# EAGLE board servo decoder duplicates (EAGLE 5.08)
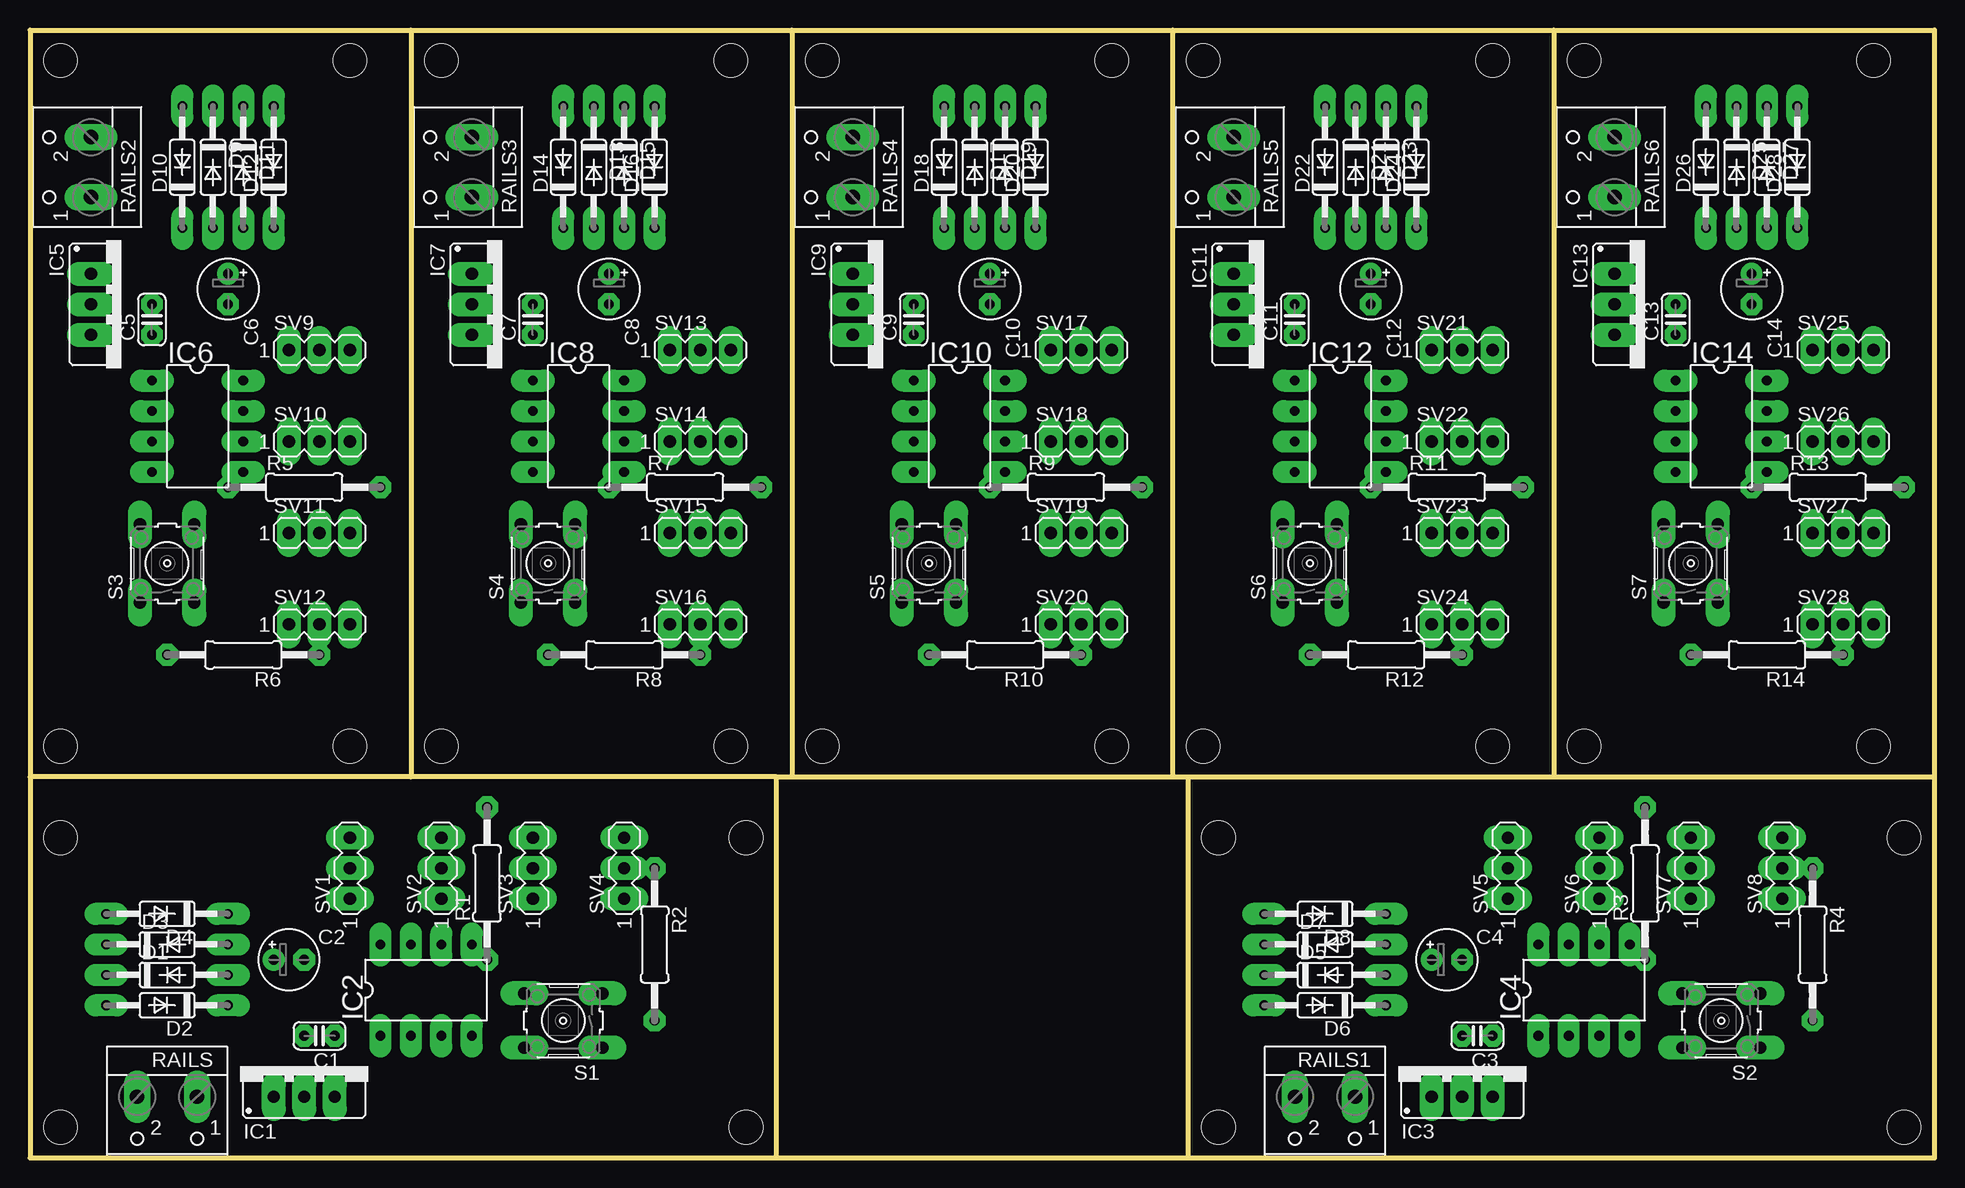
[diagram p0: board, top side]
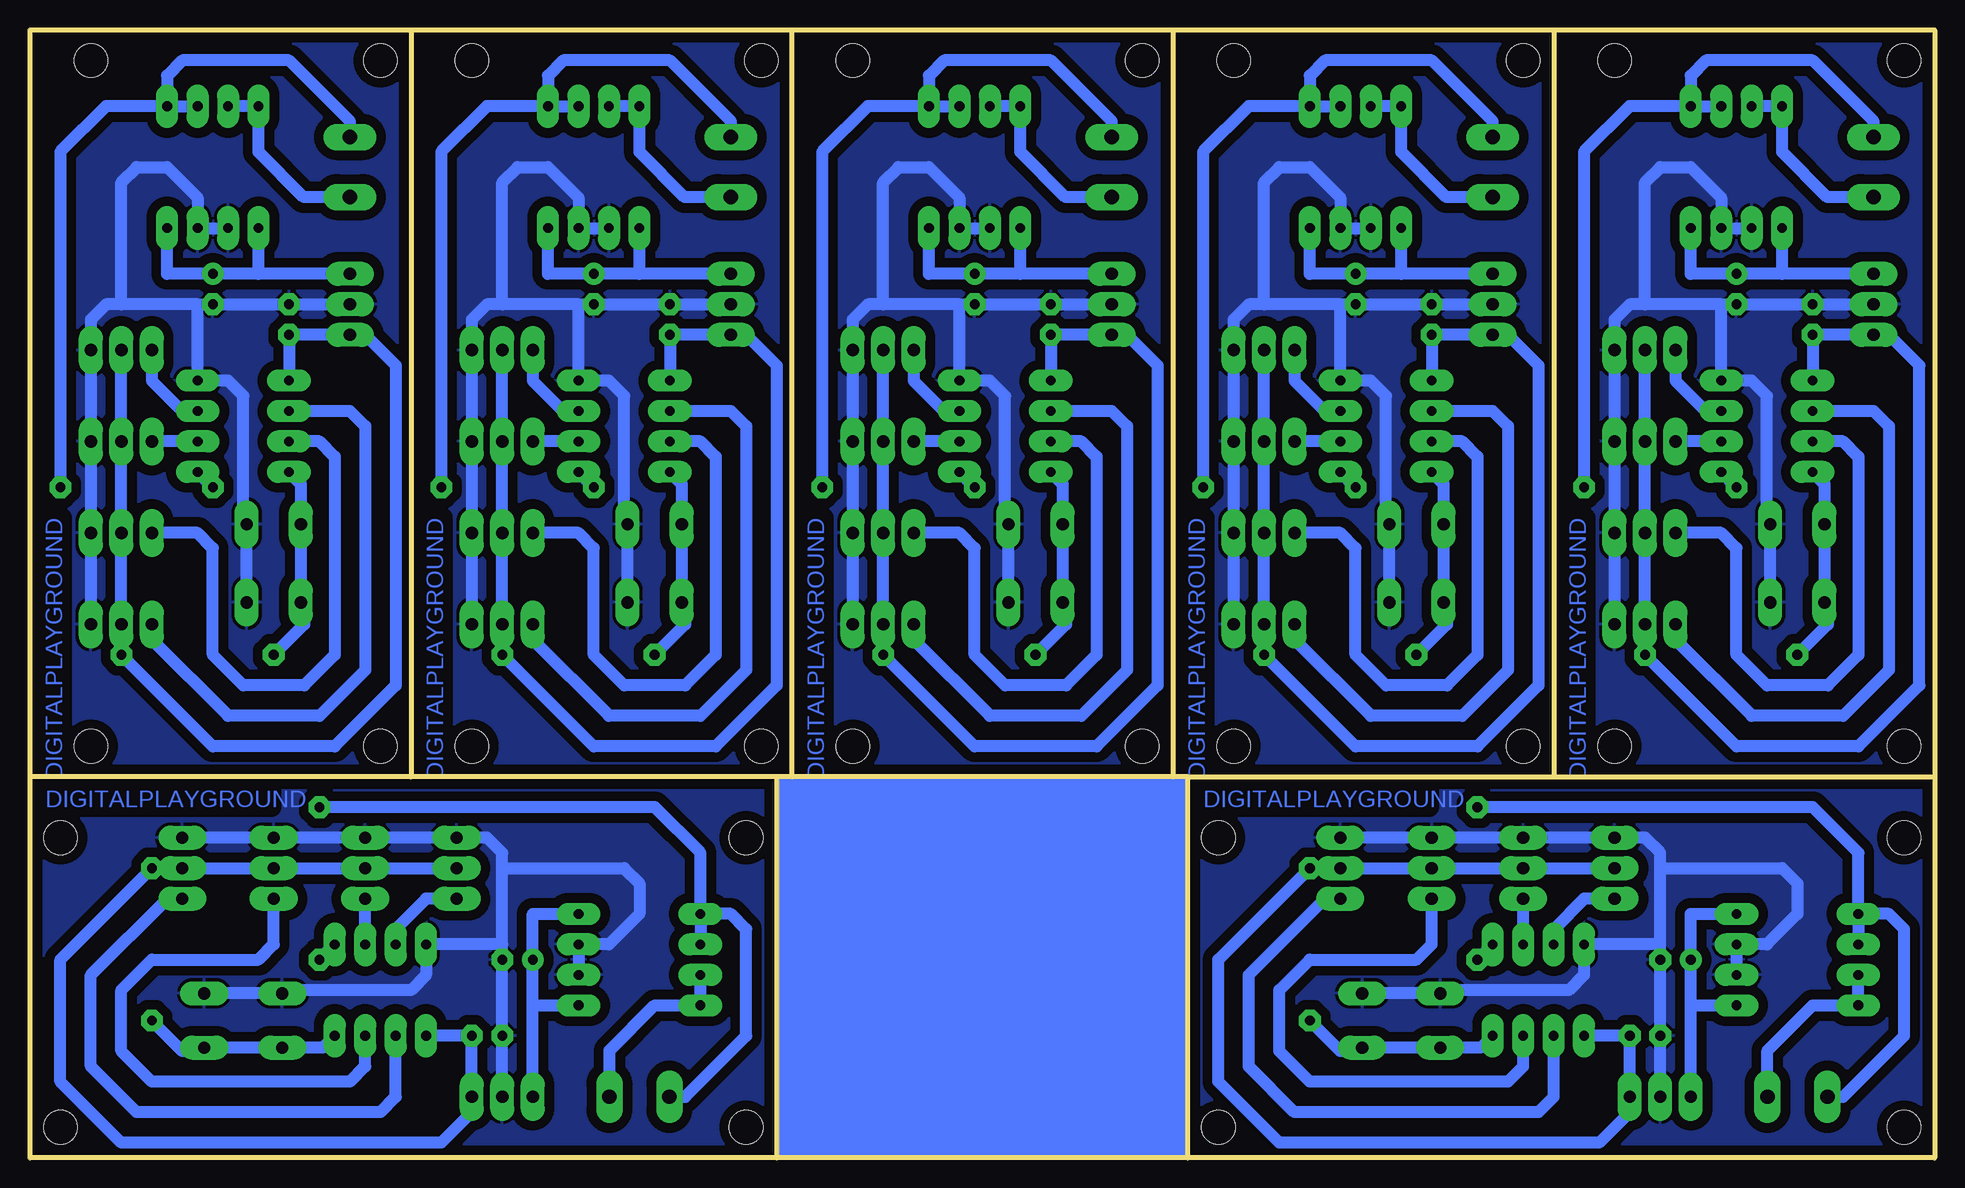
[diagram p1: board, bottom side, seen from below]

Size 158.75 x 93.98 mm. Coordinates in mm from the lower left corner, seen from the top.
Outline: 62.23,0 0,0 0,31.75
Outline: 62.23,0 96.52,0
Outline: 96.52,0 158.75,0 158.75,31.75
Outline: 158.75,31.75 158.75,93.98 127,93.98
Outline: 0,31.75 0,93.98 31.75,93.98
Outline: 62.23,0 62.23,31.75
Outline: 62.23,31.75 31.75,31.75
Outline: 31.75,31.75 0,31.75
Outline: 62.23,31.75 63.5,31.75
Outline: 63.5,31.75 95.25,31.75
Outline: 95.25,31.75 96.52,31.75
Outline: 31.75,93.98 63.5,93.98
Outline: 63.5,93.98 95.25,93.98
Outline: 31.75,93.98 31.75,31.75
Outline: 63.5,93.98 63.5,31.75
Outline: 96.52,31.75 127,31.75
Outline: 127,31.75 158.75,31.75
Outline: 96.52,31.75 96.52,0
Outline: 95.25,93.98 127,93.98
Outline: 95.25,31.75 95.25,93.98
Outline: 127,93.98 127,31.75
Copper layers (1*16): Top 0.8mm / dielectric 1.3mm / Bottom 0.8mm
Design rules "DRC settings smallest": minimum track width 0.8mm, minimum drill 24mil, track to track 0.2mm, track to pad 0.2mm, pad to pad 0.2mm, via to via 0.2mm, smd to smd 8mil, copper to edge 0.3mm, drill to drill 0.3mm, minimum pad ring 0.5mm, minimum via ring 1mm, stop-mask expansion 4mil, vias tented up to drill 0mil, thermal gap 10mil
Holes 2.8 mm at 2.54,26.67 59.69,26.67 59.69,2.54 2.54,2.54 99.06,26.67 156.21,26.67 156.21,2.54 99.06,2.54 26.67,91.44 26.67,34.29 2.54,34.29 2.54,91.44 58.42,91.44 58.42,34.29 34.29,34.29 34.29,91.44 90.17,91.44 90.17,34.29 66.04,34.29 66.04,91.44 121.92,91.44 121.92,34.29 97.79,34.29 97.79,91.44 153.67,91.44 153.67,34.29 129.54,34.29 129.54,91.44

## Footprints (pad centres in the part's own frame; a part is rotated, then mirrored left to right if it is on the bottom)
C025-024X044 = drill 0.813 octagon: 1 -1.27,0; 2 1.27,0
E2,5-5 = drill 0.813 pad 1.6 round: + -1.27,0 | drill 0.813 pad 1.6 octagon: - 1.27,0
DO35-10 = drill 0.813 long: A 5.08,0; C -5.08,0
78XXS = drill 1.016 long: GND 0,-2.54; IN -2.54,-2.54; OUT 2.54,-2.54
DIL8 = drill 0.813 long: 1 -3.81,-3.81; 2 -1.27,-3.81; 3 1.27,-3.81; 4 3.81,-3.81; 5 3.81,3.81; 6 1.27,3.81; 7 -1.27,3.81; 8 -3.81,3.81
0207/12 = drill 0.813 octagon: 1 -6.35,0; 2 6.35,0
W237-102 = drill 1.194 long: 1 -2.5,-1.27; 2 2.5,-1.27
B3F-10XX = drill 1.016 long: 1 -3.251,2.261; 2 3.251,2.261; 3 -3.251,-2.261; 4 3.251,-2.261
MA03-1 = drill 1.016 long: 1 -2.54,0; 2 0,0; 3 2.54,0

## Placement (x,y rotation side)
C1  100nF  [C025-024X044]  24.13,10.16 180 top
C2  100uF  [E2,5-5]  21.59,16.51 0 top
C3  100nF  [C025-024X044]  120.65,10.16 180 top
C4  100uF  [E2,5-5]  118.11,16.51 0 top
C5  100nF  [C025-024X044]  10.16,69.85 90 top
C6  100uF  [E2,5-5]  16.51,72.39 270 top
C7  100nF  [C025-024X044]  41.91,69.85 90 top
C8  100uF  [E2,5-5]  48.26,72.39 270 top
C9  100nF  [C025-024X044]  73.66,69.85 90 top
C10  100uF  [E2,5-5]  80.01,72.39 270 top
C11  100nF  [C025-024X044]  105.41,69.85 90 top
C12  100uF  [E2,5-5]  111.76,72.39 270 top
C13  100nF  [C025-024X044]  137.16,69.85 90 top
C14  100uF  [E2,5-5]  143.51,72.39 270 top
D1  1N4148  [DO35-10]  11.43,15.24 0 top
D2  1N4148  [DO35-10]  11.43,12.7 180 top
D3  1N4148  [DO35-10]  11.43,17.78 0 top
D4  1N4148  [DO35-10]  11.43,20.32 180 top
D5  1N4148  [DO35-10]  107.95,15.24 0 top
D6  1N4148  [DO35-10]  107.95,12.7 180 top
D7  1N4148  [DO35-10]  107.95,17.78 0 top
D8  1N4148  [DO35-10]  107.95,20.32 180 top
D9  1N4148  [DO35-10]  15.24,82.55 270 top
D10  1N4148  [DO35-10]  12.7,82.55 90 top
D11  1N4148  [DO35-10]  17.78,82.55 270 top
D12  1N4148  [DO35-10]  20.32,82.55 90 top
D13  1N4148  [DO35-10]  46.99,82.55 270 top
D14  1N4148  [DO35-10]  44.45,82.55 90 top
D15  1N4148  [DO35-10]  49.53,82.55 270 top
D16  1N4148  [DO35-10]  52.07,82.55 90 top
D17  1N4148  [DO35-10]  78.74,82.55 270 top
D18  1N4148  [DO35-10]  76.2,82.55 90 top
D19  1N4148  [DO35-10]  81.28,82.55 270 top
D20  1N4148  [DO35-10]  83.82,82.55 90 top
D21  1N4148  [DO35-10]  110.49,82.55 270 top
D22  1N4148  [DO35-10]  107.95,82.55 90 top
D23  1N4148  [DO35-10]  113.03,82.55 270 top
D24  1N4148  [DO35-10]  115.57,82.55 90 top
D25  1N4148  [DO35-10]  142.24,82.55 270 top
D26  1N4148  [DO35-10]  139.7,82.55 90 top
D27  1N4148  [DO35-10]  144.78,82.55 270 top
D28  1N4148  [DO35-10]  147.32,82.55 90 top
IC1  [78XXS]  22.86,7.62 0 top
IC2  PIC12F629P  [DIL8]  33.02,13.97 0 top
IC3  [78XXS]  119.38,7.62 0 top
IC4  PIC12F629P  [DIL8]  129.54,13.97 0 top
IC5  [78XXS]  7.62,71.12 270 top
IC6  PIC12F629P  [DIL8]  13.97,60.96 270 top
IC7  [78XXS]  39.37,71.12 270 top
IC8  PIC12F629P  [DIL8]  45.72,60.96 270 top
IC9  [78XXS]  71.12,71.12 270 top
IC10  PIC12F629P  [DIL8]  77.47,60.96 270 top
IC11  [78XXS]  102.87,71.12 270 top
IC12  PIC12F629P  [DIL8]  109.22,60.96 270 top
IC13  [78XXS]  134.62,71.12 270 top
IC14  PIC12F629P  [DIL8]  140.97,60.96 270 top
R1  22K  [0207/12]  38.1,22.86 90 top
R2  22K  [0207/12]  52.07,17.78 270 top
R3  22K  [0207/12]  134.62,22.86 90 top
R4  22K  [0207/12]  148.59,17.78 270 top
R5  22K  [0207/12]  22.86,55.88 0 top
R6  22K  [0207/12]  17.78,41.91 180 top
R7  22K  [0207/12]  54.61,55.88 0 top
R8  22K  [0207/12]  49.53,41.91 180 top
R9  22K  [0207/12]  86.36,55.88 0 top
R10  22K  [0207/12]  81.28,41.91 180 top
R11  22K  [0207/12]  118.11,55.88 0 top
R12  22K  [0207/12]  113.03,41.91 180 top
R13  22K  [0207/12]  149.86,55.88 0 top
R14  22K  [0207/12]  144.78,41.91 180 top
RAILS  [W237-102]  11.43,3.81 180 top
RAILS1  [W237-102]  107.95,3.81 180 top
RAILS2  [W237-102]  3.81,82.55 90 top
RAILS3  [W237-102]  35.56,82.55 90 top
RAILS4  [W237-102]  67.31,82.55 90 top
RAILS5  [W237-102]  99.06,82.55 90 top
RAILS6  [W237-102]  130.81,82.55 90 top
S1  [B3F-10XX]  44.45,11.43 180 top
S2  [B3F-10XX]  140.97,11.43 180 top
S3  [B3F-10XX]  11.43,49.53 90 top
S4  [B3F-10XX]  43.18,49.53 90 top
S5  [B3F-10XX]  74.93,49.53 90 top
S6  [B3F-10XX]  106.68,49.53 90 top
S7  [B3F-10XX]  138.43,49.53 90 top
SV1  [MA03-1]  26.67,24.13 90 top
SV2  [MA03-1]  34.29,24.13 90 top
SV3  [MA03-1]  41.91,24.13 90 top
SV4  [MA03-1]  49.53,24.13 90 top
SV5  [MA03-1]  123.19,24.13 90 top
SV6  [MA03-1]  130.81,24.13 90 top
SV7  [MA03-1]  138.43,24.13 90 top
SV8  [MA03-1]  146.05,24.13 90 top
SV9  [MA03-1]  24.13,67.31 0 top
SV10  [MA03-1]  24.13,59.69 0 top
SV11  [MA03-1]  24.13,52.07 0 top
SV12  [MA03-1]  24.13,44.45 0 top
SV13  [MA03-1]  55.88,67.31 0 top
SV14  [MA03-1]  55.88,59.69 0 top
SV15  [MA03-1]  55.88,52.07 0 top
SV16  [MA03-1]  55.88,44.45 0 top
SV17  [MA03-1]  87.63,67.31 0 top
SV18  [MA03-1]  87.63,59.69 0 top
SV19  [MA03-1]  87.63,52.07 0 top
SV20  [MA03-1]  87.63,44.45 0 top
SV21  [MA03-1]  119.38,67.31 0 top
SV22  [MA03-1]  119.38,59.69 0 top
SV23  [MA03-1]  119.38,52.07 0 top
SV24  [MA03-1]  119.38,44.45 0 top
SV25  [MA03-1]  151.13,67.31 0 top
SV26  [MA03-1]  151.13,59.69 0 top
SV27  [MA03-1]  151.13,52.07 0 top
SV28  [MA03-1]  151.13,44.45 0 top

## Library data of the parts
C1 C3 C5 C7 C9 C11 C13 R1-R14 = rcl
C2 C4 C6 C8 C10 C12 C14 = resistor
D1-D28 = diode
IC1 IC3 IC5 IC7 IC9 IC11 IC13 = v-reg
IC2 IC4 IC6 IC8 IC10 IC12 IC14 = microchip
RAILS RAILS1-RAILS6 = con-wago-500
S1-S7 = switch-omron
SV1-SV28 = con-lstb

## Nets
+5V/1: C1.1 IC1.OUT IC2.1 R2.1 SV1.2 SV2.2 SV3.2 SV4.2
+5V/2: C3.1 IC3.OUT IC4.1 R4.1 SV5.2 SV6.2 SV7.2 SV8.2
+5V/3: C5.1 IC5.OUT IC6.1 R6.1 SV9.2 SV10.2 SV11.2 SV12.2
+5V/4: C7.1 IC7.OUT IC8.1 R8.1 SV13.2 SV14.2 SV15.2 SV16.2
+5V/5: C9.1 IC9.OUT IC10.1 R10.1 SV17.2 SV18.2 SV19.2 SV20.2
+5V/6: C11.1 IC11.OUT IC12.1 R12.1 SV21.2 SV22.2 SV23.2 SV24.2
+5V/7: C13.1 IC13.OUT IC14.1 R14.1 SV25.2 SV26.2 SV27.2 SV28.2
GND: C1.2 C2.- D1.A D3.A IC1.GND IC2.8 S1.3 S1.4 SV1.3 SV2.3 SV3.3 SV4.3
GND1: C3.2 C4.- D5.A D7.A IC3.GND IC4.8 S2.3 S2.4 SV5.3 SV6.3 SV7.3 SV8.3
GND2: C5.2 C6.- D9.A D11.A IC5.GND IC6.8 S3.3 S3.4 SV9.3 SV10.3 SV11.3 SV12.3
GND3: C7.2 C8.- D13.A D15.A IC7.GND IC8.8 S4.3 S4.4 SV13.3 SV14.3 SV15.3 SV16.3
GND4: C9.2 C10.- D17.A D19.A IC9.GND IC10.8 S5.3 S5.4 SV17.3 SV18.3 SV19.3 SV20.3
GND5: C11.2 C12.- D21.A D23.A IC11.GND IC12.8 S6.3 S6.4 SV21.3 SV22.3 SV23.3 SV24.3
GND6: C13.2 C14.- D25.A D27.A IC13.GND IC14.8 S7.3 S7.4 SV25.3 SV26.3 SV27.3 SV28.3
N$1: D1.C D2.A RAILS.1
N$2: D3.C D4.A R1.2 RAILS.2
N$3: D5.C D6.A RAILS1.1
N$4: C2.+ D2.C D4.C IC1.IN
N$5: IC2.7 SV1.1
N$6: IC2.6 SV2.1
N$7: IC2.3 SV3.1
N$8: IC2.2 SV4.1
N$9: IC2.5 R1.1
N$10: IC2.4 R2.2 S1.1 S1.2
N$11: D7.C D8.A R3.2 RAILS1.2
N$12: C4.+ D6.C D8.C IC3.IN
N$13: IC4.7 SV5.1
N$14: IC4.6 SV6.1
N$15: IC4.3 SV7.1
N$16: IC4.2 SV8.1
N$17: IC4.5 R3.1
N$18: IC4.4 R4.2 S2.1 S2.2
N$19: D9.C D10.A RAILS2.1
N$20: D11.C D12.A R5.2 RAILS2.2
N$21: C6.+ D10.C D12.C IC5.IN
N$22: IC6.7 SV9.1
N$23: IC6.6 SV10.1
N$24: IC6.3 SV11.1
N$25: IC6.2 SV12.1
N$26: IC6.5 R5.1
N$27: IC6.4 R6.2 S3.1 S3.2
N$28: D13.C D14.A RAILS3.1
N$29: D15.C D16.A R7.2 RAILS3.2
N$30: C8.+ D14.C D16.C IC7.IN
N$31: IC8.7 SV13.1
N$32: IC8.6 SV14.1
N$33: IC8.3 SV15.1
N$34: IC8.2 SV16.1
N$35: IC8.5 R7.1
N$36: IC8.4 R8.2 S4.1 S4.2
N$37: D17.C D18.A RAILS4.1
N$38: D19.C D20.A R9.2 RAILS4.2
N$39: C10.+ D18.C D20.C IC9.IN
N$40: IC10.7 SV17.1
N$41: IC10.6 SV18.1
N$42: IC10.3 SV19.1
N$43: IC10.2 SV20.1
N$44: IC10.5 R9.1
N$45: IC10.4 R10.2 S5.1 S5.2
N$46: D21.C D22.A RAILS5.1
N$47: D23.C D24.A R11.2 RAILS5.2
N$48: C12.+ D22.C D24.C IC11.IN
N$49: IC12.7 SV21.1
N$50: IC12.6 SV22.1
N$51: IC12.3 SV23.1
N$52: IC12.2 SV24.1
N$53: IC12.5 R11.1
N$54: IC12.4 R12.2 S6.1 S6.2
N$55: D25.C D26.A RAILS6.1
N$56: D27.C D28.A R13.2 RAILS6.2
N$57: C14.+ D26.C D28.C IC13.IN
N$58: IC14.7 SV25.1
N$59: IC14.6 SV26.1
N$60: IC14.3 SV27.1
N$61: IC14.2 SV28.1
N$62: IC14.5 R13.1
N$63: IC14.4 R14.2 S7.1 S7.2

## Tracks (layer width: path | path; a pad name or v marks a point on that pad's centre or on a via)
+5V/1
  Bottom 1.016: IC2.1 C1.1 IC1.OUT 25.4,3.81 27.94,1.27 54.61,1.27 59.69,6.35 59.69,16.51 R2.1 SV4.2 SV3.2 SV2.2 SV1.2
+5V/2
  Bottom 1.016: IC4.1 C3.1 IC3.OUT 121.92,3.81 124.46,1.27 151.13,1.27 156.21,6.35 156.21,16.51 R4.1 SV8.2 SV7.2 SV6.2 SV5.2
+5V/3
  Bottom 1.016: IC6.1 C5.1 IC5.OUT 3.81,68.58 1.27,66.04 1.27,39.37 6.35,34.29 16.51,34.29 R6.1 SV12.2 SV11.2 SV10.2 SV9.2
+5V/4
  Bottom 1.016: IC8.1 C7.1 IC7.OUT 35.56,68.58 33.02,66.04 33.02,39.37 38.1,34.29 48.26,34.29 R8.1 SV16.2 SV15.2 SV14.2 SV13.2
+5V/5
  Bottom 1.016: IC10.1 C9.1 IC9.OUT 67.31,68.58 64.77,66.04 64.77,39.37 69.85,34.29 80.01,34.29 R10.1 SV20.2 SV19.2 SV18.2 SV17.2
+5V/6
  Bottom 1.016: IC12.1 C11.1 IC11.OUT 99.06,68.58 96.52,66.04 96.52,39.37 101.6,34.29 111.76,34.29 R12.1 SV24.2 SV23.2 SV22.2 SV21.2
+5V/7
  Bottom 1.016: IC14.1 C13.1 IC13.OUT 130.81,68.58 128.27,66.04 128.27,39.37 133.35,34.29 143.51,34.29 R14.1 SV28.2 SV27.2 SV26.2 SV25.2
GND
  Bottom 1.016: S1.3 S1.4 40.92,13.97 30.48,13.97 29.21,15.24 IC2.8 22.86,17.78 | IC1.GND C1.2 C2.- 22.86,17.78 | SV4.3 SV3.3 SV2.3 SV1.3 24.13,26.67 22.86,25.4 22.86,24.13 | 22.86,17.78 22.86,24.13 | D1.A D3.A 13.97,17.78 11.43,20.32 11.43,22.86 12.7,24.13 22.86,24.13
  pour Bottom (isolate 0.813): 0,31.75 62.23,31.75 62.23,0 0,0
GND1
  Bottom 1.016: S2.3 S2.4 137.44,13.97 127,13.97 125.73,15.24 IC4.8 119.38,17.78 | IC3.GND C3.2 C4.- 119.38,17.78 | SV8.3 SV7.3 SV6.3 SV5.3 120.65,26.67 119.38,25.4 119.38,24.13 | 119.38,17.78 119.38,24.13 | D5.A D7.A 110.49,17.78 107.95,20.32 107.95,22.86 109.22,24.13 119.38,24.13
  pour Bottom (isolate 0.813): 96.52,31.75 158.75,31.75 158.75,0 96.52,0
GND2
  Bottom 1.016: S3.3 S3.4 13.97,53.06 13.97,63.5 15.24,64.77 IC6.8 17.78,71.12 | IC5.GND C5.2 C6.- 17.78,71.12 | SV12.3 SV11.3 SV10.3 SV9.3 26.67,69.85 25.4,71.12 24.13,71.12 | 17.78,71.12 24.13,71.12 | D9.A D11.A 17.78,80.01 20.32,82.55 22.86,82.55 24.13,81.28 24.13,71.12
  pour Bottom (isolate 0.813): 0,93.98 31.75,93.98 31.75,31.75 0,31.75
GND3
  Bottom 1.016: S4.3 S4.4 45.72,53.06 45.72,63.5 46.99,64.77 IC8.8 49.53,71.12 | IC7.GND C7.2 C8.- 49.53,71.12 | SV16.3 SV15.3 SV14.3 SV13.3 58.42,69.85 57.15,71.12 55.88,71.12 | 49.53,71.12 55.88,71.12 | D13.A D15.A 49.53,80.01 52.07,82.55 54.61,82.55 55.88,81.28 55.88,71.12
  pour Bottom (isolate 0.813): 31.75,93.98 63.5,93.98 63.5,31.75 31.75,31.75
GND4
  Bottom 1.016: S5.3 S5.4 77.47,53.06 77.47,63.5 78.74,64.77 IC10.8 81.28,71.12 | IC9.GND C9.2 C10.- 81.28,71.12 | SV20.3 SV19.3 SV18.3 SV17.3 90.17,69.85 88.9,71.12 87.63,71.12 | 81.28,71.12 87.63,71.12 | D17.A D19.A 81.28,80.01 83.82,82.55 86.36,82.55 87.63,81.28 87.63,71.12
  pour Bottom (isolate 0.813): 63.5,93.98 95.25,93.98 95.25,31.75 63.5,31.75
GND5
  Bottom 1.016: S6.3 S6.4 109.22,53.06 109.22,63.5 110.49,64.77 IC12.8 113.03,71.12 | IC11.GND C11.2 C12.- 113.03,71.12 | SV24.3 SV23.3 SV22.3 SV21.3 121.92,69.85 120.65,71.12 119.38,71.12 | 113.03,71.12 119.38,71.12 | D21.A D23.A 113.03,80.01 115.57,82.55 118.11,82.55 119.38,81.28 119.38,71.12
  pour Bottom (isolate 0.813): 95.25,93.98 127,93.98 127,31.75 95.25,31.75
GND6
  Bottom 1.016: S7.3 S7.4 140.97,53.06 140.97,63.5 142.24,64.77 IC14.8 144.78,71.12 | IC13.GND C13.2 C14.- 144.78,71.12 | SV28.3 SV27.3 SV26.3 SV25.3 153.67,69.85 152.4,71.12 151.13,71.12 | 144.78,71.12 151.13,71.12 | D25.A D27.A 144.78,80.01 147.32,82.55 149.86,82.55 151.13,81.28 151.13,71.12
  pour Bottom (isolate 0.813): 127,93.98 158.75,93.98 158.75,31.75 127,31.75
N$1
  Bottom 1.016: D1.C D2.A 10.16,12.7 13.93,8.93 RAILS.1
N$2
  Bottom 1.016: R1.2 10.16,29.21 6.35,25.4 D4.A | RAILS.2 7.62,5.08 2.54,10.16 2.54,19.05 3.81,20.32 D4.A | D4.A D3.C
N$3
  Bottom 1.016: D5.C D6.A 106.68,12.7 110.45,8.93 RAILS1.1
N$4
  Bottom 1.016: IC1.IN 20.32,12.7 | 20.32,12.7 C2.+ 20.32,20.32 D4.C | 20.32,12.7 D2.C
N$5
  Bottom 1.016: IC2.7 31.75,19.05 29.21,21.59 SV1.1
N$6
  Bottom 1.016: IC2.6 SV2.1
N$7
  Bottom 1.016: IC2.3 34.29,7.62 35.56,6.35 52.07,6.35 54.61,8.89 54.61,13.97 52.07,16.51 43.18,16.51 41.91,17.78 SV3.1
N$8
  Bottom 1.016: IC2.2 31.75,5.08 33.02,3.81 53.34,3.81 57.15,7.62 57.15,15.24 50.8,21.59 SV4.1
N$9
  Bottom 1.016: R1.1 IC2.5
N$10
  Bottom 1.016: IC2.4 37.82,9.17 S1.2 S1.1 47.98,8.89 49.53,8.89 R2.2
N$11
  Bottom 1.016: R3.2 106.68,29.21 102.87,25.4 D8.A | RAILS1.2 104.14,5.08 99.06,10.16 99.06,19.05 100.33,20.32 D8.A | D8.A D7.C
N$12
  Bottom 1.016: IC3.IN 116.84,12.7 | 116.84,12.7 C4.+ 116.84,20.32 D8.C | 116.84,12.7 D6.C
N$13
  Bottom 1.016: IC4.7 128.27,19.05 125.73,21.59 SV5.1
N$14
  Bottom 1.016: IC4.6 SV6.1
N$15
  Bottom 1.016: IC4.3 130.81,7.62 132.08,6.35 148.59,6.35 151.13,8.89 151.13,13.97 148.59,16.51 139.7,16.51 138.43,17.78 SV7.1
N$16
  Bottom 1.016: IC4.2 128.27,5.08 129.54,3.81 149.86,3.81 153.67,7.62 153.67,15.24 147.32,21.59 SV8.1
N$17
  Bottom 1.016: R3.1 IC4.5
N$18
  Bottom 1.016: IC4.4 134.34,9.17 S2.2 S2.1 144.5,8.89 146.05,8.89 R4.2
N$19
  Bottom 1.016: D9.C D10.A 12.7,83.82 8.93,80.05 RAILS2.1
N$20
  Bottom 1.016: R5.2 29.21,83.82 25.4,87.63 D12.A | RAILS2.2 5.08,86.36 10.16,91.44 19.05,91.44 20.32,90.17 D12.A | D12.A D11.C
N$21
  Bottom 1.016: IC5.IN 12.7,73.66 | 12.7,73.66 C6.+ 20.32,73.66 D12.C | 12.7,73.66 D10.C
N$22
  Bottom 1.016: IC6.7 19.05,62.23 21.59,64.77 SV9.1
N$23
  Bottom 1.016: IC6.6 SV10.1
N$24
  Bottom 1.016: IC6.3 7.62,59.69 6.35,58.42 6.35,41.91 8.89,39.37 13.97,39.37 16.51,41.91 16.51,50.8 17.78,52.07 SV11.1
N$25
  Bottom 1.016: IC6.2 5.08,62.23 3.81,60.96 3.81,40.64 7.62,36.83 15.24,36.83 21.59,43.18 SV12.1
N$26
  Bottom 1.016: R5.1 IC6.5
N$27
  Bottom 1.016: IC6.4 9.17,56.16 S3.2 S3.1 8.89,46 8.89,44.45 R6.2
N$28
  Bottom 1.016: D13.C D14.A 44.45,83.82 40.68,80.05 RAILS3.1
N$29
  Bottom 1.016: R7.2 60.96,83.82 57.15,87.63 D16.A | RAILS3.2 36.83,86.36 41.91,91.44 50.8,91.44 52.07,90.17 D16.A | D16.A D15.C
N$30
  Bottom 1.016: IC7.IN 44.45,73.66 | 44.45,73.66 C8.+ 52.07,73.66 D16.C | 44.45,73.66 D14.C
N$31
  Bottom 1.016: IC8.7 50.8,62.23 53.34,64.77 SV13.1
N$32
  Bottom 1.016: IC8.6 SV14.1
N$33
  Bottom 1.016: IC8.3 39.37,59.69 38.1,58.42 38.1,41.91 40.64,39.37 45.72,39.37 48.26,41.91 48.26,50.8 49.53,52.07 SV15.1
N$34
  Bottom 1.016: IC8.2 36.83,62.23 35.56,60.96 35.56,40.64 39.37,36.83 46.99,36.83 53.34,43.18 SV16.1
N$35
  Bottom 1.016: R7.1 IC8.5
N$36
  Bottom 1.016: IC8.4 40.92,56.16 S4.2 S4.1 40.64,46 40.64,44.45 R8.2
N$37
  Bottom 1.016: D17.C D18.A 76.2,83.82 72.43,80.05 RAILS4.1
N$38
  Bottom 1.016: R9.2 92.71,83.82 88.9,87.63 D20.A | RAILS4.2 68.58,86.36 73.66,91.44 82.55,91.44 83.82,90.17 D20.A | D20.A D19.C
N$39
  Bottom 1.016: IC9.IN 76.2,73.66 | 76.2,73.66 C10.+ 83.82,73.66 D20.C | 76.2,73.66 D18.C
N$40
  Bottom 1.016: IC10.7 82.55,62.23 85.09,64.77 SV17.1
N$41
  Bottom 1.016: IC10.6 SV18.1
N$42
  Bottom 1.016: IC10.3 71.12,59.69 69.85,58.42 69.85,41.91 72.39,39.37 77.47,39.37 80.01,41.91 80.01,50.8 81.28,52.07 SV19.1
N$43
  Bottom 1.016: IC10.2 68.58,62.23 67.31,60.96 67.31,40.64 71.12,36.83 78.74,36.83 85.09,43.18 SV20.1
N$44
  Bottom 1.016: R9.1 IC10.5
N$45
  Bottom 1.016: IC10.4 72.67,56.16 S5.2 S5.1 72.39,46 72.39,44.45 R10.2
N$46
  Bottom 1.016: D21.C D22.A 107.95,83.82 104.18,80.05 RAILS5.1
N$47
  Bottom 1.016: R11.2 124.46,83.82 120.65,87.63 D24.A | RAILS5.2 100.33,86.36 105.41,91.44 114.3,91.44 115.57,90.17 D24.A | D24.A D23.C
N$48
  Bottom 1.016: IC11.IN 107.95,73.66 | 107.95,73.66 C12.+ 115.57,73.66 D24.C | 107.95,73.66 D22.C
N$49
  Bottom 1.016: IC12.7 114.3,62.23 116.84,64.77 SV21.1
N$50
  Bottom 1.016: IC12.6 SV22.1
N$51
  Bottom 1.016: IC12.3 102.87,59.69 101.6,58.42 101.6,41.91 104.14,39.37 109.22,39.37 111.76,41.91 111.76,50.8 113.03,52.07 SV23.1
N$52
  Bottom 1.016: IC12.2 100.33,62.23 99.06,60.96 99.06,40.64 102.87,36.83 110.49,36.83 116.84,43.18 SV24.1
N$53
  Bottom 1.016: R11.1 IC12.5
N$54
  Bottom 1.016: IC12.4 104.42,56.16 S6.2 S6.1 104.14,46 104.14,44.45 R12.2
N$55
  Bottom 1.016: D25.C D26.A 139.7,83.82 135.93,80.05 RAILS6.1
N$56
  Bottom 1.016: R13.2 156.21,83.82 152.4,87.63 D28.A | RAILS6.2 132.08,86.36 137.16,91.44 146.05,91.44 147.32,90.17 D28.A | D28.A D27.C
N$57
  Bottom 1.016: IC13.IN 139.7,73.66 | 139.7,73.66 C14.+ 147.32,73.66 D28.C | 139.7,73.66 D26.C
N$58
  Bottom 1.016: IC14.7 146.05,62.23 148.59,64.77 SV25.1
N$59
  Bottom 1.016: IC14.6 SV26.1
N$60
  Bottom 1.016: IC14.3 134.62,59.69 133.35,58.42 133.35,41.91 135.89,39.37 140.97,39.37 143.51,41.91 143.51,50.8 144.78,52.07 SV27.1
N$61
  Bottom 1.016: IC14.2 132.08,62.23 130.81,60.96 130.81,40.64 134.62,36.83 142.24,36.83 148.59,43.18 SV28.1
N$62
  Bottom 1.016: R13.1 IC14.5
N$63
  Bottom 1.016: IC14.4 136.17,56.16 S7.2 S7.1 135.89,46 135.89,44.45 R14.2
(copper drawn outside any net)
  shapes: Bottom area x1

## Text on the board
Bottom: DIGITALPLAYGROUND | DIGITALPLAYGROUND | DIGITALPLAYGROUND | DIGITALPLAYGROUND | DIGITALPLAYGROUND | DIGITALPLAYGROUND | DIGITALPLAYGROUND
